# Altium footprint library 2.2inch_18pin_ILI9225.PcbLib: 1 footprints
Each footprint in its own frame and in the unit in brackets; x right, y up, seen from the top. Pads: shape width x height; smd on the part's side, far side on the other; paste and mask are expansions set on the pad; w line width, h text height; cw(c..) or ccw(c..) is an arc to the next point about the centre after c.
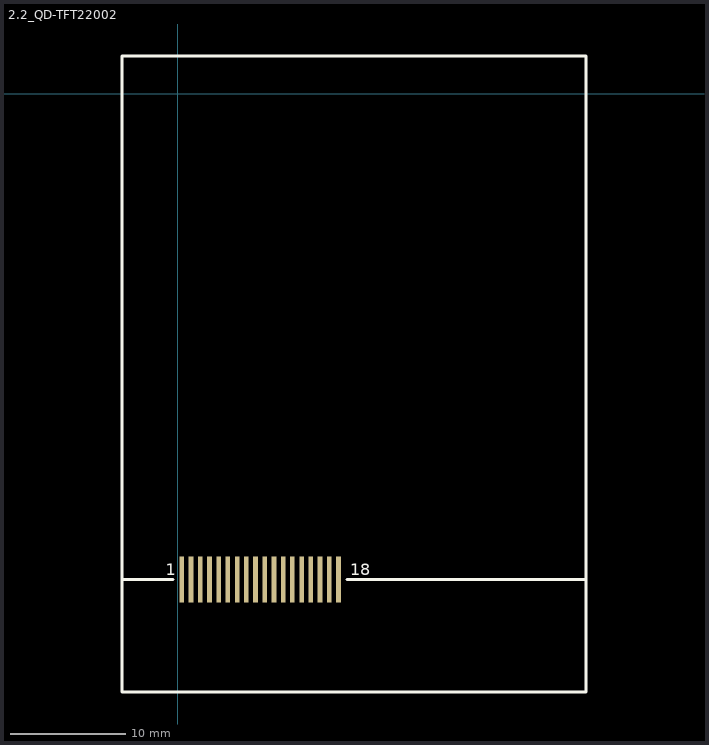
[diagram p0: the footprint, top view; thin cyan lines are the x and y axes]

## 2.2_QD-TFT22002 [mm] "LCD"
pads (18):
  rect 0.4x4 smd: 1(0.374,-42.158) 2(1.174,-42.158) 3(1.974,-42.158) 4(2.774,-42.158) 5(3.574,-42.158) 6(4.374,-42.158) 7(5.174,-42.158) 8(5.974,-42.158) 9(6.774,-42.158) 10(7.574,-42.158) 11(8.374,-42.158) 12(9.174,-42.158) 13(9.974,-42.158) 14(10.774,-42.158) 15(11.574,-42.158) 16(12.374,-42.158) 17(13.174,-42.158) 18(13.974,-42.158)
Top Overlay:
  lines w0.254: -4.826,-42.158 -0.381,-42.158 ; 14.732,-42.158 35.474,-42.158 ; -4.826,-51.958 35.474,-51.958 35.474,3.302 -4.826,3.302 -4.826,-51.958
  text "18" at 14.986,-41.783 h1.02
  text "1" at -1.016,-41.783 h1.02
